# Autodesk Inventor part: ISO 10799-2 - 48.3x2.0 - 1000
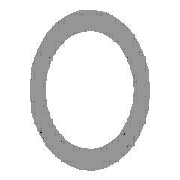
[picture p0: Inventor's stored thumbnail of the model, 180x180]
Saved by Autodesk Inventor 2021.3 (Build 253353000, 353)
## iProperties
IsCustomPart: 1
_CCFamilyMember: 14
_CCFamilyDisplayName: ISO 10799-2 (Profils creux circulaires - Formés à froid) - Aciers de construction - Coupes creuses profilées formées à froid, soudées
_FrameMemberDoc: Frame Member File
_Version: 25.0.0
_GetPNFromCC: 1
Created: 2018-07
Part Number: ISO 10799-2 - 48.3x2.0 - 1000
Material: Acier, doux
Description: Aciers de construction - Coupes creuses profilées formées à froid, soudées
Document SubType Name: Modeling
Standard: ISO
Designer: Fabian Perrée
Standard Revision: First edition 2011-09-15
Standards Organization: ISO
Language: fr-FR
Size Designation: 48.3x2.0
Categories: <MemberInstance><Categories><Category DisplayName="Profilés" InternalName="089c4875-fa83-4c05-b084-43b9cc11f5ed" Mnemonic="GRDR"><CategoryParameter DisplayName=
Stock Number: 48.3x2.0
Density: 7.85 g/cm^3
Appearance: Semi-poli
Mass: 2283.66 g
Surface Area: 2914.93 cm^2
Volume: 290.911 cm^3
G_L: 1000,000 mm
G_W: 48,300 mm
G_H: 48,300 mm
Author: Fabian Perrée
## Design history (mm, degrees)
node "Plan de départ"
node "Plan de fin"
sketch "Esquisse"
  geometry: C1 r 22.15 at (0, 0); C2 r 24.15 at (0, 0); 2 further points
  constraints: 3 coincident, 2 centre point
  dimensions: "d0" = 48.3 diameter of C2 (= G_H); "d1" = 2 radial gap between concentric circles of C2 C1 (= G_T)
extrude "Corps" new body sketch "Esquisse" stored distance "d2" = 1000 (= G_L); taper "d3" = 0 deg
node "Driven Length"
  sketch "Sketch3"
    geometry: L1 (0, 0)-(10, 0) reference
    constraints: 2 end point, 1 horizontal
  workplane "Work Plane3"
  sketch "Sketch4"
    geometry: L1 (-2, 0)-(12, 0) reference; L2 (-2, 1000)-(12, 1000) reference
    dimensions: "d7" = 1000 distance between parallel lines of L1 L2 (derived)
body "Solid1"
other parameters: "G_H" = 48.3 [user parameter; used in 1 equation term], "G_T" = 2 [user parameter; used in 1 equation term], "G_L" = 1000 (= d7) [user parameter; used in 1 equation term], "G_OFFSET_START" = 0 [user parameter; used in 1 equation term], "G_OFFSET_END" = 0 [user parameter; used in 1 equation term], "d4" = 0 (computed from G_OFFSET_START), "d6" = 90 deg, "MAS" = 0.228 [user parameter]
